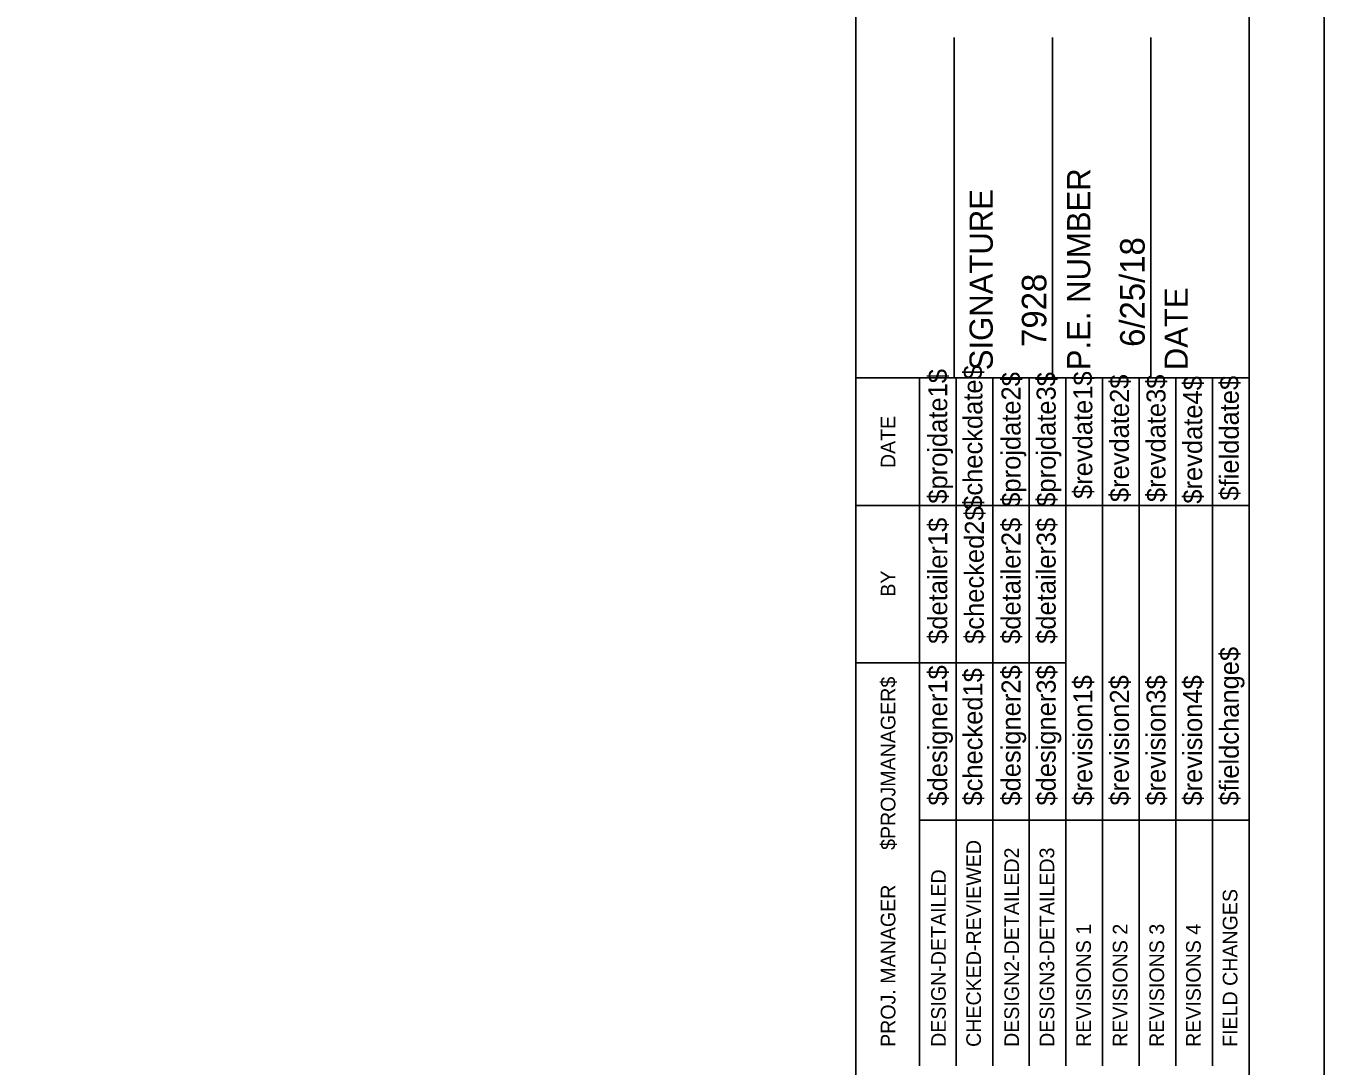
# Model space of a CAD drawing. Extents: x 916251 to 917164, y 328941 to 329491.
# Drawn here: x 916935.8 to 917100.9, y 329181.4 to 329313.6 of the extents above; entities that cross this region are included whole.
import ezdxf

# ---------------------------------------------------------------- set-up
doc = ezdxf.new("R2010")
doc.units = 0
doc.layers.add('ANNOTATION', color=7, linetype='Continuous')
doc.layers.add('elec-detail-ext-post-mtd-meter-panel', color=7, linetype='Continuous')

msp = doc.modelspace()

# ---------------------------------------------------------------- linework, layer by layer
at = {"layer": 'ANNOTATION'}
msp.add_lwpolyline([(916250.87, 328941.08), (917100.87, 328941.08), (917100.87, 329491.08), (916250.87, 329491.08)], close=True, dxfattribs=at)
at = {"layer": 'elec-detail-ext-post-mtd-meter-panel'}
for p, q in [((917041.34, 328956.39), (917041.34, 329481.39)), ((917091.34, 328956.39), (917091.34, 329481.39)), ((917053.84, 329268.89), (917053.84, 329312.13)), ((917066.34, 329268.89), (917066.34, 329312.13)), ((917078.84, 329268.89), (917078.84, 329312.13)), ((917041.34, 329268.89), (917091.34, 329268.89))]:
    msp.add_line(p, q, dxfattribs=at)
for points in [[(917049.41, 329252.64), (917049.41, 329268.89)], [(917054.07, 329181.41), (917054.07, 329268.89)], [(917058.73, 329268.89), (917058.73, 329181.41)], [(917063.39, 329181.41), (917063.39, 329268.89)], [(917068.05, 329181.41), (917068.05, 329268.89)], [(917072.71, 329181.41), (917072.71, 329268.89)], [(917077.36, 329181.41), (917077.36, 329268.89)], [(917082.02, 329181.41), (917082.02, 329268.89)], [(917086.68, 329181.41), (917086.68, 329268.89)], [(917049.41, 329181.41), (917049.41, 329265.36)], [(917041.34, 329252.64), (917091.34, 329252.64)], [(917041.34, 329232.64), (917049.41, 329232.64)], [(917049.41, 329232.64), (917068.04, 329232.64)], [(917049.41, 329212.64), (917091.34, 329212.64)]]:
    msp.add_lwpolyline(points, dxfattribs=at)

# ---------------------------------------------------------------- texts
for s, height, p in [('P.E. NUMBER', 2.9528, (917071.14, 329269.85)), ('SIGNATURE', 2.953, (917058.74, 329269.85)), ('6/25/18', 3.125, (917078.06, 329272.82)), ('7928', 3.125, (917065.56, 329272.82)), ('DATE', 2.953, (917083.54, 329269.85)), ('$projdate1$', 2.4227, (917052.95, 329252.89)), ('$checkdate$', 2.4227, (917057.42, 329252.11)), ('$projdate2$', 2.4227, (917062.27, 329252.5)), ('$projdate3$', 2.4227, (917066.74, 329252.5)), ('$revdate1$', 2.423, (917071.4, 329253.49)), ('$revdate2$', 2.423, (917076.06, 329253.09)), ('$revdate3$', 2.423, (917080.71, 329253.09)), ('$revdate4$', 2.423, (917085.37, 329252.89)), ('$fielddate$', 2.4227, (917090.03, 329253.29)), ('DATE', 1.857, (917046.36, 329257.42)), ('$checked2$', 2.423, (917057.61, 329235.07)), ('$detailer1$', 2.4227, (917052.95, 329235.07)), ('$detailer2$', 2.4227, (917062.27, 329235.07)), ('$detailer3$', 2.4227, (917066.74, 329235.07)), ('BY', 1.857, (917046.36, 329241.07)), ('$fieldchange$', 2.4227, (917090.03, 329214.51)), ('$designer1$', 2.4227, (917052.95, 329214.51)), ('$checked1$', 2.423, (917057.42, 329214.51)), ('$designer2$', 2.4227, (917062.27, 329214.51)), ('$designer3$', 2.4227, (917066.74, 329214.51)), ('$PROJMANAGER$', 1.8637, (917046.36, 329208.87)), ('$revision1$', 2.4227, (917071.4, 329214.51)), ('$revision2$', 2.4227, (917076.06, 329214.51)), ('$revision3$', 2.4227, (917080.71, 329214.51)), ('$revision4$', 2.4227, (917085.37, 329214.51)), ('CHECKED-REVIEWED', 1.8637, (917057.24, 329183.83)), ('DESIGN2-DETAILED2', 1.8637, (917062.08, 329183.83)), ('DESIGN3-DETAILED3', 1.8637, (917066.56, 329183.83)), ('DESIGN-DETAILED', 1.8637, (917052.77, 329183.83)), ('PROJ. MANAGER', 1.8637, (917046.36, 329183.83)), ('FIELD CHANGES', 1.8637, (917089.85, 329183.83)), ('REVISIONS 1', 1.8637, (917071.22, 329183.83)), ('REVISIONS 2', 1.8637, (917075.87, 329183.83)), ('REVISIONS 3', 1.8637, (917080.53, 329183.83)), ('REVISIONS 4', 1.8637, (917085.19, 329183.83))]:
    msp.add_text(s, height=height, rotation=90, dxfattribs=at).set_placement(p)

doc.saveas('drawing.dxf')
